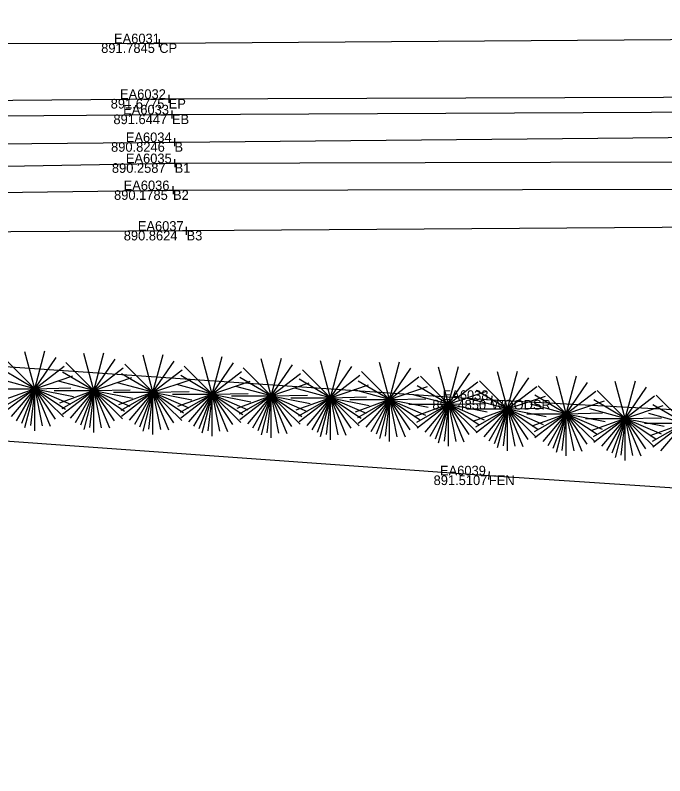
# Model space of a CAD drawing. Extents: x 179044 to 189691, y 286531 to 301257.
# Drawn here: x 179753.2 to 179834.1, y 300496.5 to 300591.3 of the extents above; entities that cross this region are included whole.
import ezdxf

# ---------------------------------------------------------------- set-up
doc = ezdxf.new("R2010")
doc.units = 0
for name, color, linetype in [('PV_X_COP', 7, 'Continuous'), ('PV_X_EOP', 7, 'Continuous'), ('PV_X_Shoulder_Aggregate', 7, 'Continuous'), ('RD_X_Fence', 7, 'Continuous'), ('SV_X_Break_Lines', 7, 'Continuous'), ('SV_X_Shot_Marker', 7, 'Continuous'), ('SV_X_Text_Comment', 7, 'Continuous'), ('SV_X_Text_Elevation', 7, 'Continuous'), ('SV_X_Text_Name', 7, 'Continuous'), ('VG_X_Cells', 7, 'Continuous'), ('VG_X_Text', 7, 'Continuous'), ('VG_X_Tree_Line_Lt', 7, 'Continuous')]:
    doc.layers.add(name, color=color, linetype=linetype)

msp = doc.modelspace()

# ---------------------------------------------------------------- linework, layer by layer
at = {"layer": 'PV_X_COP'}
msp.add_lwpolyline([(179370.611, 300584.893), (179476.831, 300585.936), (179562.951, 300586.92), (179659.852, 300587.603), (179771.173, 300587.773), (179881.154, 300588.595), (179985.728, 300588.166), (180079.826, 300588.612), (180147.691, 300589.874), (180172.034, 300590.636), (180187.456, 300591.905), (180203.618, 300593.325)], dxfattribs=at)
at = {"layer": 'PV_X_EOP'}
msp.add_lwpolyline([(179371.146, 300578.051), (179477.168, 300579.528), (179563.012, 300579.455), (179660.626, 300579.907), (179772.349, 300580.843), (179883.302, 300581.216), (179986.953, 300581.659), (180080.461, 300581.624), (180131.142, 300581.875), (180152.421, 300580.897), (180177.372, 300581.245), (180192.481, 300580.813), (180205.116, 300578.916), (180211.895, 300576.366), (180217.061, 300570.924), (180226.256, 300546.032), (180252.64, 300475.662), (180284.891, 300388.784), (180312.046, 300315.753), (180341.998, 300235.308)], dxfattribs=at)
at = {"layer": 'PV_X_Shoulder_Aggregate'}
msp.add_lwpolyline([(179563.451, 300578.229), (179660.977, 300578.016), (179772.748, 300578.901), (179883.7, 300579.446), (179986.895, 300579.719), (180080.262, 300579.655), (180131.517, 300579.632), (180152.892, 300578.404), (180177.169, 300578.87), (180192.854, 300577.824), (180203.732, 300575.396), (180212.869, 300569.272), (180224.05, 300544.426), (180250.422, 300474.503), (180282.665, 300386.992), (180309.922, 300313.986), (180339.844, 300234.334)], dxfattribs=at)
at = {"layer": 'RD_X_Fence'}
msp.add_lwpolyline([(179565.425, 300550.823), (179667.832, 300544.252), (179812.225, 300533.926), (179896.206, 300528.356), (179941.193, 300525.399), (180078.773, 300515.902), (180168.337, 300509.719), (180196.88, 300447.723), (180266.667, 300296.146), (180285.875, 300252.935)], dxfattribs=at)
at = {"layer": 'SV_X_Break_Lines'}
for points in [[(179565.115, 300573.15), (179662.025, 300574.398), (179773.068, 300575.457), (179882.867, 300576.482), (179986.954, 300576.827), (180079.906, 300577.073), (180132.276, 300575.162), (180173.558, 300573.472), (180187.352, 300573.774), (180198.853, 300570.766)], [(179565.766, 300571.109), (179663.199, 300570.888), (179773.087, 300572.831), (179882.326, 300573.106), (179987.447, 300574.391), (180079.006, 300574.101), (180132.144, 300569.99), (180164.614, 300565.351), (180185.409, 300564.026)], [(179565.763, 300567.872), (179663.335, 300568.017), (179772.883, 300569.466), (179881.609, 300569.697), (179987.857, 300571.139), (180079.155, 300570.638), (180132.418, 300565.887), (180165.824, 300561.088), (180185.221, 300560.101)], [(180320.902, 300212.184), (180282.069, 300307.438), (180254.033, 300376.286), (180214.216, 300457.225), (180192.833, 300518.475), (180187.002, 300524.649), (180178.544, 300551.918), (180167.492, 300556.189), (180133.433, 300560.27), (180078.668, 300564.705), (179988.563, 300564.714), (179881.16, 300565.14), (179774.574, 300564.41), (179665.201, 300563.792), (179565.532, 300563.693)]]:
    msp.add_lwpolyline(points, dxfattribs=at)
at = {"layer": 'SV_X_Shot_Marker'}
for p, q in [((179771.172, 300588.273), (179771.174, 300587.273)), ((179770.673, 300587.772), (179771.673, 300587.774)), ((179771.173, 300587.773), (179771.173, 300587.773)), ((179772.345, 300581.343), (179772.354, 300580.343)), ((179771.85, 300580.839), (179772.849, 300580.847)), ((179772.349, 300580.843), (179772.349, 300580.843)), ((179772.744, 300579.401), (179772.752, 300578.401)), ((179772.248, 300578.897), (179773.248, 300578.905)), ((179772.748, 300578.901), (179772.748, 300578.901)), ((179773.063, 300575.957), (179773.073, 300574.957)), ((179772.568, 300575.452), (179773.568, 300575.461)), ((179773.068, 300575.457), (179773.068, 300575.457)), ((179772.587, 300572.822), (179773.587, 300572.84)), ((179773.078, 300573.331), (179773.096, 300572.331)), ((179773.087, 300572.831), (179773.087, 300572.831)), ((179772.876, 300569.966), (179772.89, 300568.966)), ((179772.383, 300569.459), (179773.383, 300569.472)), ((179772.883, 300569.466), (179772.883, 300569.466)), ((179775.074, 300564.413), (179774.074, 300564.406)), ((179774.577, 300563.91), (179774.57, 300564.91)), ((179774.574, 300564.41), (179774.574, 300564.41)), ((179812.047, 300543.37), (179813.044, 300543.302)), ((179812.58, 300543.835), (179812.511, 300542.837)), ((179812.545, 300543.336), (179812.545, 300543.336)), ((179811.726, 300533.962), (179812.724, 300533.89)), ((179812.261, 300534.425), (179812.189, 300533.427)), ((179812.225, 300533.926), (179812.225, 300533.926))]:
    msp.add_line(p, q, dxfattribs=at)
at = {"layer": 'VG_X_Cells'}
for p, q in [((179755.66, 300544.733), (179754.425, 300549.346)), ((179755.66, 300544.733), (179756.916, 300549.431)), ((179763.024, 300544.508), (179761.789, 300549.122)), ((179763.024, 300544.508), (179764.28, 300549.207)), ((179755.66, 300544.733), (179752.17, 300548.219)), ((179755.66, 300544.733), (179758.315, 300548.618)), ((179763.024, 300544.508), (179765.679, 300548.393)), ((179770.388, 300544.284), (179769.153, 300548.898)), ((179770.388, 300544.284), (179771.645, 300548.983)), ((179770.388, 300544.284), (179773.043, 300548.169)), ((179777.753, 300544.06), (179776.518, 300548.674)), ((179777.753, 300544.06), (179779.01, 300548.759)), ((179785.118, 300543.836), (179783.883, 300548.449)), ((179785.118, 300543.836), (179786.375, 300548.534)), ((179792.485, 300543.612), (179791.25, 300548.225)), ((179792.485, 300543.612), (179793.741, 300548.31)), ((179799.852, 300543.39), (179801.109, 300548.088)), ((179755.66, 300544.733), (179759.316, 300547.538)), ((179763.024, 300544.508), (179759.534, 300547.995)), ((179763.024, 300544.508), (179766.68, 300547.313)), ((179770.388, 300544.284), (179766.898, 300547.771)), ((179777.753, 300544.06), (179774.263, 300547.547)), ((179777.753, 300544.06), (179780.408, 300547.945)), ((179785.118, 300543.836), (179781.628, 300547.323)), ((179785.118, 300543.836), (179787.773, 300547.721)), ((179792.485, 300543.612), (179795.14, 300547.497)), ((179799.852, 300543.39), (179798.617, 300548.003)), ((179799.852, 300543.39), (179802.507, 300547.275)), ((179807.19, 300542.8), (179805.955, 300547.413)), ((179807.19, 300542.8), (179808.447, 300547.498)), ((179755.66, 300544.733), (179751.753, 300547.029)), ((179755.66, 300544.733), (179760.396, 300546.339)), ((179763.024, 300544.508), (179759.117, 300546.805)), ((179770.388, 300544.284), (179766.481, 300546.581)), ((179770.388, 300544.284), (179774.045, 300547.089)), ((179777.753, 300544.06), (179773.846, 300546.357)), ((179777.753, 300544.06), (179781.41, 300546.865)), ((179785.118, 300543.836), (179788.775, 300546.641)), ((179792.485, 300543.612), (179788.995, 300547.099)), ((179792.485, 300543.612), (179796.141, 300546.417)), ((179799.852, 300543.39), (179796.362, 300546.877)), ((179799.852, 300543.39), (179803.509, 300546.195)), ((179807.19, 300542.8), (179803.7, 300546.287)), ((179807.19, 300542.8), (179809.845, 300546.685)), ((179814.529, 300542.21), (179813.294, 300546.823)), ((179814.529, 300542.21), (179815.785, 300546.908)), ((179821.867, 300541.62), (179820.632, 300546.233)), ((179821.867, 300541.62), (179823.123, 300546.318)), ((179755.66, 300544.733), (179751.246, 300545.916)), ((179763.024, 300544.508), (179758.61, 300545.692)), ((179763.024, 300544.508), (179767.76, 300546.115)), ((179770.388, 300544.284), (179765.975, 300545.468)), ((179770.388, 300544.284), (179775.125, 300545.891)), ((179777.753, 300544.06), (179773.34, 300545.244)), ((179777.753, 300544.06), (179782.49, 300545.667)), ((179785.118, 300543.836), (179781.212, 300546.133)), ((179785.118, 300543.836), (179789.855, 300545.443)), ((179792.485, 300543.612), (179788.578, 300545.909)), ((179792.485, 300543.612), (179797.221, 300545.219)), ((179799.852, 300543.39), (179795.945, 300545.687)), ((179807.19, 300542.8), (179810.847, 300545.605)), ((179814.529, 300542.21), (179811.039, 300545.697)), ((179814.529, 300542.21), (179817.184, 300546.095)), ((179821.867, 300541.62), (179824.522, 300545.505)), ((179829.205, 300541.03), (179827.97, 300545.643)), ((179829.205, 300541.03), (179830.462, 300545.728)), ((179750.725, 300544.733), (179755.66, 300544.733)), ((179755.66, 300544.733), (179751.37, 300543.171)), ((179755.66, 300544.733), (179751.676, 300542.451)), ((179755.66, 300544.733), (179751.753, 300541.738)), ((179755.66, 300544.733), (179752.715, 300541.266)), ((179755.66, 300544.733), (179753.341, 300540.718)), ((179755.66, 300544.733), (179753.995, 300540.393)), ((179755.66, 300544.733), (179754.396, 300539.876)), ((179755.66, 300544.733), (179755.118, 300540.141)), ((179755.66, 300544.733), (179760.17, 300544.824)), ((179755.66, 300539.493), (179755.66, 300544.733)), ((179755.66, 300544.733), (179756.581, 300540.096)), ((179755.66, 300544.733), (179757.593, 300540.064)), ((179755.66, 300544.733), (179758.196, 300540.939)), ((179755.66, 300544.733), (179759.248, 300541.211)), ((179755.66, 300544.733), (179759.481, 300542.178)), ((179755.66, 300544.733), (179760.125, 300542.791)), ((179755.66, 300544.733), (179760.488, 300543.774)), ((179758.089, 300544.508), (179763.024, 300544.508)), ((179763.024, 300544.508), (179758.734, 300542.947)), ((179763.024, 300544.508), (179759.04, 300542.227)), ((179763.024, 300544.508), (179759.117, 300541.513)), ((179763.024, 300544.508), (179760.079, 300541.042)), ((179763.024, 300544.508), (179760.705, 300540.493)), ((179763.024, 300544.508), (179761.359, 300540.168)), ((179763.024, 300544.508), (179761.76, 300539.652)), ((179763.024, 300544.508), (179762.482, 300539.917)), ((179763.024, 300544.508), (179767.534, 300544.6)), ((179763.024, 300539.268), (179763.024, 300544.508)), ((179763.024, 300544.508), (179763.945, 300539.872)), ((179763.024, 300544.508), (179764.957, 300539.84)), ((179763.024, 300544.508), (179765.56, 300540.715)), ((179763.024, 300544.508), (179766.612, 300540.987)), ((179763.024, 300544.508), (179766.845, 300541.953)), ((179763.024, 300544.508), (179767.489, 300542.567)), ((179763.024, 300544.508), (179767.852, 300543.55)), ((179765.453, 300544.284), (179770.388, 300544.284)), ((179770.388, 300544.284), (179766.098, 300542.723)), ((179770.388, 300544.284), (179766.405, 300542.003)), ((179770.388, 300544.284), (179766.481, 300541.289)), ((179770.388, 300544.284), (179767.443, 300540.818)), ((179770.388, 300544.284), (179768.07, 300540.269)), ((179770.388, 300544.284), (179768.723, 300539.944)), ((179770.388, 300544.284), (179769.125, 300539.428)), ((179770.388, 300544.284), (179769.846, 300539.693)), ((179770.388, 300544.284), (179774.898, 300544.376)), ((179770.388, 300539.044), (179770.388, 300544.284)), ((179770.388, 300544.284), (179771.31, 300539.648)), ((179770.388, 300544.284), (179772.321, 300539.616)), ((179770.388, 300544.284), (179772.925, 300540.491)), ((179770.388, 300544.284), (179773.976, 300540.763)), ((179770.388, 300544.284), (179774.21, 300541.729)), ((179770.388, 300544.284), (179774.853, 300542.343)), ((179770.388, 300544.284), (179775.216, 300543.326)), ((179785.118, 300543.836), (179780.705, 300545.019)), ((179792.485, 300543.612), (179788.071, 300544.795)), ((179799.852, 300543.39), (179795.439, 300544.573)), ((179799.852, 300543.39), (179804.589, 300544.997)), ((179807.19, 300542.8), (179803.284, 300545.097)), ((179807.19, 300542.8), (179811.927, 300544.407)), ((179814.529, 300542.21), (179810.622, 300544.507)), ((179814.529, 300542.21), (179818.185, 300545.015)), ((179821.867, 300541.62), (179818.377, 300545.107)), ((179821.867, 300541.62), (179825.523, 300544.425)), ((179829.205, 300541.03), (179825.715, 300544.517)), ((179829.205, 300541.03), (179831.86, 300544.915)), ((179772.818, 300544.06), (179777.753, 300544.06)), ((179777.753, 300544.06), (179773.463, 300542.499)), ((179777.753, 300544.06), (179773.77, 300541.779)), ((179777.753, 300544.06), (179773.846, 300541.065)), ((179777.753, 300544.06), (179774.808, 300540.594)), ((179777.753, 300544.06), (179775.435, 300540.045)), ((179777.753, 300544.06), (179776.088, 300539.72)), ((179777.753, 300544.06), (179776.49, 300539.204)), ((179777.753, 300544.06), (179777.211, 300539.469)), ((179777.753, 300544.06), (179782.263, 300544.152)), ((179777.753, 300538.82), (179777.753, 300544.06)), ((179777.753, 300544.06), (179778.675, 300539.424)), ((179777.753, 300544.06), (179779.686, 300539.392)), ((179777.753, 300544.06), (179780.29, 300540.267)), ((179777.753, 300544.06), (179781.341, 300540.539)), ((179777.753, 300544.06), (179781.575, 300541.505)), ((179777.753, 300544.06), (179782.218, 300542.119)), ((179777.753, 300544.06), (179782.581, 300543.102)), ((179780.183, 300543.836), (179785.118, 300543.836)), ((179785.118, 300543.836), (179780.828, 300542.274)), ((179785.118, 300543.836), (179781.135, 300541.554)), ((179785.118, 300543.836), (179781.212, 300540.841)), ((179785.118, 300543.836), (179782.173, 300540.369)), ((179785.118, 300543.836), (179782.8, 300539.821)), ((179785.118, 300543.836), (179783.453, 300539.496)), ((179785.118, 300543.836), (179783.855, 300538.979)), ((179785.118, 300543.836), (179784.577, 300539.244)), ((179785.118, 300543.836), (179789.628, 300543.928)), ((179785.118, 300538.596), (179785.118, 300543.836)), ((179785.118, 300543.836), (179786.04, 300539.199)), ((179785.118, 300543.836), (179787.052, 300539.168)), ((179785.118, 300543.836), (179787.655, 300540.043)), ((179785.118, 300543.836), (179788.707, 300540.314)), ((179785.118, 300543.836), (179788.94, 300541.281)), ((179785.118, 300543.836), (179789.583, 300541.894)), ((179785.118, 300543.836), (179789.947, 300542.878)), ((179787.55, 300543.612), (179792.485, 300543.612)), ((179792.485, 300543.612), (179788.195, 300542.05)), ((179792.485, 300543.612), (179788.501, 300541.33)), ((179792.485, 300543.612), (179788.578, 300540.617)), ((179792.485, 300543.612), (179789.54, 300540.145)), ((179792.485, 300543.612), (179790.166, 300539.597)), ((179792.485, 300543.612), (179790.82, 300539.272)), ((179792.485, 300543.612), (179791.221, 300538.755)), ((179792.485, 300543.612), (179791.943, 300539.02)), ((179792.485, 300543.612), (179796.995, 300543.704)), ((179792.485, 300538.372), (179792.485, 300543.612)), ((179792.485, 300543.612), (179793.406, 300538.975)), ((179792.485, 300543.612), (179794.418, 300538.944)), ((179792.485, 300543.612), (179795.021, 300539.819)), ((179792.485, 300543.612), (179796.073, 300540.09)), ((179792.485, 300543.612), (179796.306, 300541.057)), ((179792.485, 300543.612), (179796.95, 300541.67)), ((179792.485, 300543.612), (179797.313, 300542.654)), ((179794.917, 300543.39), (179799.852, 300543.39)), ((179799.852, 300543.39), (179795.562, 300541.828)), ((179799.852, 300543.39), (179795.869, 300541.108)), ((179799.852, 300543.39), (179795.945, 300540.395)), ((179799.852, 300543.39), (179796.907, 300539.923)), ((179799.852, 300543.39), (179797.534, 300539.375)), ((179799.852, 300543.39), (179798.187, 300539.05)), ((179799.852, 300543.39), (179798.589, 300538.533)), ((179799.852, 300543.39), (179799.31, 300538.798)), ((179799.852, 300543.39), (179804.362, 300543.482)), ((179799.852, 300538.15), (179799.852, 300543.39)), ((179799.852, 300543.39), (179800.774, 300538.753)), ((179799.852, 300543.39), (179801.785, 300538.722)), ((179799.852, 300543.39), (179802.389, 300539.597)), ((179799.852, 300543.39), (179803.44, 300539.868)), ((179799.852, 300543.39), (179803.674, 300540.835)), ((179799.852, 300543.39), (179804.317, 300541.448)), ((179799.852, 300543.39), (179804.68, 300542.432)), ((179807.19, 300542.8), (179802.777, 300543.983)), ((179814.529, 300542.21), (179810.115, 300543.393)), ((179814.529, 300542.21), (179819.265, 300543.817)), ((179821.867, 300541.62), (179817.96, 300543.917)), ((179829.205, 300541.03), (179825.298, 300543.327)), ((179829.205, 300541.03), (179832.862, 300543.835)), ((179836.543, 300540.44), (179833.053, 300543.927)), ((179802.255, 300542.8), (179807.19, 300542.8)), ((179807.19, 300542.8), (179802.9, 300541.238)), ((179807.19, 300542.8), (179803.207, 300540.518)), ((179807.19, 300542.8), (179803.284, 300539.805)), ((179807.19, 300542.8), (179804.245, 300539.333)), ((179807.19, 300542.8), (179804.872, 300538.785)), ((179807.19, 300542.8), (179805.525, 300538.46)), ((179807.19, 300542.8), (179805.927, 300537.943)), ((179807.19, 300542.8), (179806.649, 300538.208)), ((179807.19, 300542.8), (179811.7, 300542.892)), ((179807.19, 300537.56), (179807.19, 300542.8)), ((179807.19, 300542.8), (179808.112, 300538.163)), ((179807.19, 300542.8), (179809.124, 300538.132)), ((179807.19, 300542.8), (179809.727, 300539.007)), ((179807.19, 300542.8), (179810.779, 300539.278)), ((179807.19, 300542.8), (179811.012, 300540.245)), ((179807.19, 300542.8), (179811.655, 300540.858)), ((179807.19, 300542.8), (179812.019, 300541.842)), ((179821.867, 300541.62), (179817.453, 300542.803)), ((179821.867, 300541.62), (179826.603, 300543.227)), ((179829.205, 300541.03), (179833.942, 300542.637)), ((179836.543, 300540.44), (179832.637, 300542.737)), ((179809.594, 300542.21), (179814.529, 300542.21)), ((179814.529, 300542.21), (179810.239, 300540.648)), ((179814.529, 300542.21), (179810.545, 300539.928)), ((179814.529, 300542.21), (179810.622, 300539.215)), ((179814.529, 300542.21), (179811.584, 300538.743)), ((179814.529, 300542.21), (179812.21, 300538.195)), ((179814.529, 300542.21), (179812.864, 300537.87)), ((179814.529, 300542.21), (179813.265, 300537.353)), ((179814.529, 300542.21), (179813.987, 300537.618)), ((179814.529, 300542.21), (179819.039, 300542.302)), ((179814.529, 300536.97), (179814.529, 300542.21)), ((179814.529, 300542.21), (179815.45, 300537.573)), ((179814.529, 300542.21), (179816.462, 300537.542)), ((179814.529, 300542.21), (179817.065, 300538.417)), ((179814.529, 300542.21), (179818.117, 300538.688)), ((179814.529, 300542.21), (179818.35, 300539.655)), ((179814.529, 300542.21), (179818.994, 300540.268)), ((179814.529, 300542.21), (179819.357, 300541.252)), ((179816.932, 300541.62), (179821.867, 300541.62)), ((179821.867, 300541.62), (179817.577, 300540.058)), ((179821.867, 300541.62), (179817.883, 300539.338)), ((179821.867, 300541.62), (179817.96, 300538.625)), ((179821.867, 300541.62), (179818.922, 300538.153)), ((179821.867, 300541.62), (179819.548, 300537.605)), ((179821.867, 300541.62), (179820.202, 300537.28)), ((179821.867, 300541.62), (179820.603, 300536.763)), ((179821.867, 300541.62), (179821.325, 300537.028)), ((179821.867, 300541.62), (179826.377, 300541.712)), ((179821.867, 300536.38), (179821.867, 300541.62)), ((179821.867, 300541.62), (179822.788, 300536.983)), ((179821.867, 300541.62), (179823.8, 300536.952)), ((179821.867, 300541.62), (179824.403, 300537.827)), ((179821.867, 300541.62), (179825.455, 300538.098)), ((179821.867, 300541.62), (179825.688, 300539.065)), ((179821.867, 300541.62), (179826.332, 300539.678)), ((179821.867, 300541.62), (179826.695, 300540.662)), ((179829.205, 300541.03), (179824.792, 300542.213)), ((179836.543, 300540.44), (179832.13, 300541.623)), ((179824.27, 300541.03), (179829.205, 300541.03)), ((179829.205, 300541.03), (179824.915, 300539.468)), ((179829.205, 300541.03), (179825.222, 300538.748)), ((179829.205, 300541.03), (179825.298, 300538.035)), ((179829.205, 300541.03), (179826.26, 300537.563)), ((179829.205, 300541.03), (179826.887, 300537.015)), ((179829.205, 300541.03), (179827.54, 300536.69)), ((179829.205, 300541.03), (179827.942, 300536.173)), ((179829.205, 300541.03), (179828.663, 300536.438)), ((179829.205, 300541.03), (179833.715, 300541.122)), ((179829.205, 300535.79), (179829.205, 300541.03)), ((179829.205, 300541.03), (179830.127, 300536.393)), ((179829.205, 300541.03), (179831.138, 300536.362)), ((179829.205, 300541.03), (179831.742, 300537.237)), ((179829.205, 300541.03), (179832.793, 300537.508)), ((179829.205, 300541.03), (179833.027, 300538.475)), ((179829.205, 300541.03), (179833.67, 300539.088)), ((179829.205, 300541.03), (179834.033, 300540.072)), ((179831.608, 300540.44), (179836.543, 300540.44)), ((179836.543, 300540.44), (179832.253, 300538.878)), ((179836.543, 300540.44), (179832.56, 300538.158)), ((179836.543, 300540.44), (179832.637, 300537.445)), ((179836.543, 300540.44), (179833.598, 300536.973))]:
    msp.add_line(p, q, dxfattribs=at)
at = {"layer": 'VG_X_Tree_Line_Lt'}
msp.add_lwpolyline([(179569.069, 300551.827), (179569.572, 300561.616), (179669.01, 300553.205), (179812.545, 300543.336), (179895.927, 300538.89), (179941.238, 300534.37), (180108.398, 300524.388), (180109.229, 300515.004)], dxfattribs=at)

# ---------------------------------------------------------------- texts
at = {"layer": 'SV_X_Text_Comment'}
for s, height, p in [('CP', 1.2, (179771.173, 300586.573)), ('EP', 1.2, (179772.349, 300579.643)), ('EB', 1.2, (179772.748, 300577.701)), ('B', 1.2, (179773.068, 300574.257)), ('B1', 1.2, (179773.087, 300571.631)), ('B2', 1.2, (179772.883, 300568.266)), ('B3', 1.2, (179774.574, 300563.21)), ('TE', 0.12, (179755.66, 300544.613)), ('TE', 0.12, (179763.024, 300544.388)), ('TE', 0.12, (179770.388, 300544.164)), ('TE', 0.12, (179777.753, 300543.94)), ('TE', 0.12, (179785.118, 300543.716)), ('TE', 0.12, (179792.485, 300543.492)), ('TE', 0.12, (179799.852, 300543.27)), ('WOODSR', 1.2, (179812.545, 300542.136)), ('TE', 0.12, (179807.19, 300542.68)), ('TE', 0.12, (179814.529, 300542.09)), ('TE', 0.12, (179821.867, 300541.5)), ('TE', 0.12, (179829.205, 300540.91)), ('FEN', 1.2, (179812.225, 300532.726))]:
    msp.add_text(s, height=height, dxfattribs=at).set_placement(p)
at = {"layer": 'SV_X_Text_Elevation'}
for s, p in [('891.7845', (179763.937, 300586.573)), ('891.6775', (179765.122, 300579.643)), ('891.6447', (179765.464, 300577.701)), ('890.8246', (179765.17, 300574.257)), ('890.2587', (179765.273, 300571.631)), ('890.1785', (179765.542, 300568.266)), ('890.8624', (179766.75, 300563.21)), ('891.4850', (179805.186, 300542.136)), ('891.5107', (179805.338, 300532.726))]:
    msp.add_text(s, height=1.2, dxfattribs=at).set_placement(p)
at = {"layer": 'SV_X_Text_Name'}
for s, p in [('EA6031', (179765.536, 300587.773)), ('EA6032', (179766.284, 300580.843)), ('EA6033', (179766.673, 300578.901)), ('EA6034', (179767.003, 300575.457)), ('EA6035', (179767.012, 300572.831)), ('EA6036', (179766.733, 300569.466)), ('EA6037', (179768.499, 300564.41)), ('EA6038', (179806.461, 300543.336)), ('EA6039', (179806.14, 300533.926))]:
    msp.add_text(s, height=1.2, dxfattribs=at).set_placement(p)
at = {"layer": 'VG_X_Text'}
for p in [(179755.66, 300544.733), (179763.024, 300544.508), (179770.388, 300544.284), (179777.753, 300544.06), (179785.118, 300543.836), (179792.485, 300543.612), (179799.852, 300543.39), (179807.19, 300542.8), (179814.529, 300542.21), (179821.867, 300541.62), (179829.205, 300541.03)]:
    msp.add_text(' NOTE:8', height=0.12, dxfattribs=at).set_placement(p)

doc.saveas('drawing.dxf')
